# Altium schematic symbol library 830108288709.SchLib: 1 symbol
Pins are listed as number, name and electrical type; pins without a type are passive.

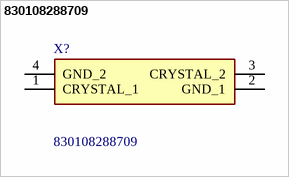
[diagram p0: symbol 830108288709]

## 830108288709
designator X?
Standard 3.2 x 2.5mm SMD crystal in a ceramic package with a seam sealed metal lid, hermetically sealed; Manufacturer_Name: Wurth Elektronik; Geometry.Height: 0.5mm
footprint 830108288709
pins: 1 CRYSTAL_1, 2 GND_1, 3 CRYSTAL_2, 4 GND_2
